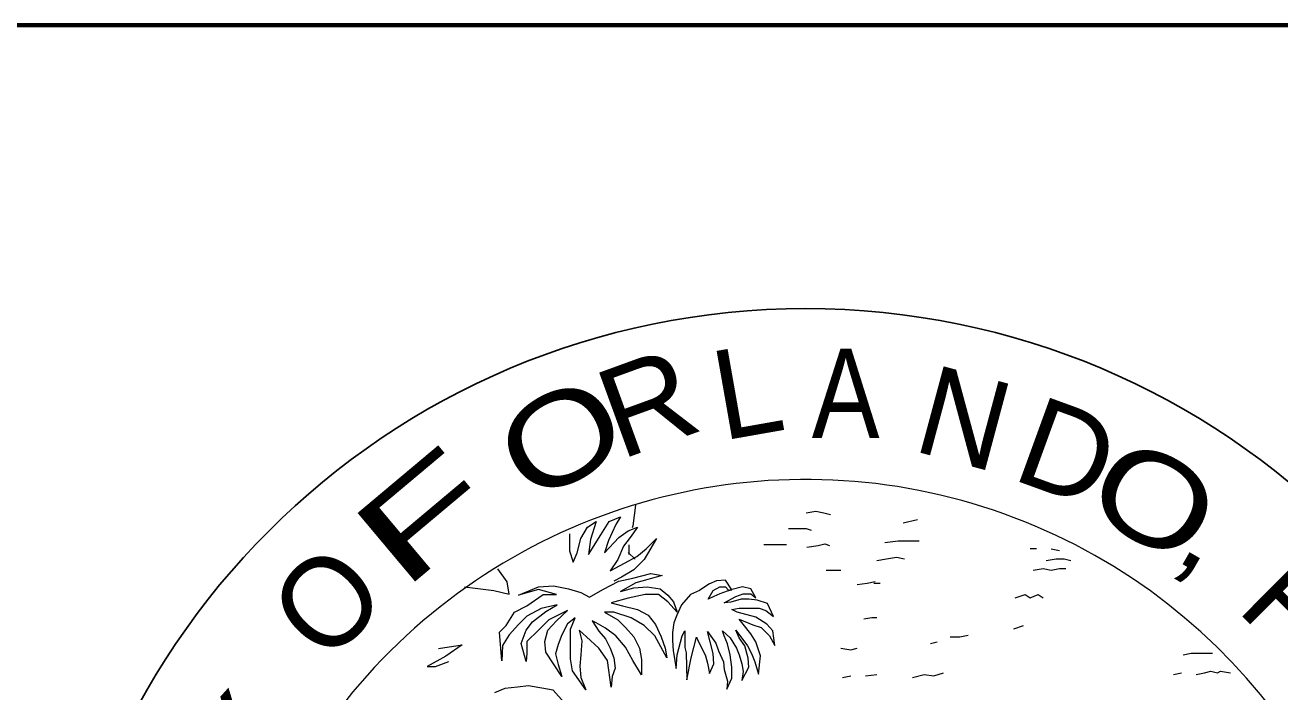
# Model space of a CAD drawing. Extents: x 44.6 to 61.6, y -38.7 to -27.7.
# Drawn here: x 46.005 to 46.645, y -37.305 to -36.965 of the extents above; entities that cross this region are included whole.
import ezdxf
from ezdxf.enums import TextEntityAlignment as Align

# ---------------------------------------------------------------- set-up
doc = ezdxf.new("R2010")
doc.units = 0
doc.header["$LTSCALE"] = 0.025
doc.layers.add('60', color=7, linetype='Continuous', lineweight=13)

msp = doc.modelspace()

# ---------------------------------------------------------------- linework, layer by layer
at = {"layer": '60', "lineweight": 70}
msp.add_line((48.84124, -36.96462), (44.82119, -36.96462), dxfattribs=at)
at = {"layer": '60'}
for p, q in [((46.45297, -37.21851), (46.46042, -37.21686)), ((46.31307, -37.22979), (46.31307, -37.23475)), ((46.31272, -37.23374), (46.31639, -37.23711)), ((46.52111, -37.23182), (46.51776, -37.23182)), ((46.52858, -37.23182), (46.53274, -37.23268)), ((46.43801, -37.24929), (46.44129, -37.24929)), ((46.50944, -37.27259), (46.51441, -37.2709)), ((46.46703, -37.28004), (46.4704, -37.27919)), ((46.42218, -37.2975), (46.42631, -37.29666)), ((46.4338, -37.29666), (46.43961, -37.29582)), ((46.59091, -37.29582), (46.59507, -37.295))]:
    msp.add_line(p, q, dxfattribs=at)
for points in [[(46.31657, -37.20958), (46.31586, -37.21485), (46.31516, -37.22007), (46.31473, -37.22114)], [(46.2829, -37.22417), (46.2829, -37.23284), (46.28478, -37.23862), (46.28672, -37.23383), (46.28864, -37.22657), (46.29208, -37.22076), (46.29639, -37.21787), (46.2935, -37.22705), (46.29251, -37.23475), (46.29877, -37.22466), (46.30315, -37.21787), (46.30892, -37.21545), (46.3065, -37.21934), (46.30266, -37.22757), (46.30074, -37.23383), (46.30797, -37.22605), (46.31274, -37.22268), (46.31761, -37.22076), (46.31371, -37.22605), (46.31038, -37.23043), (46.30745, -37.23721), (46.30362, -37.24293), (46.31083, -37.2391), (46.31711, -37.23572), (46.32194, -37.23184), (46.32728, -37.22657), (46.32097, -37.23721), (46.31565, -37.24248), (46.30941, -37.24633), (46.30551, -37.24827)], [(46.4035, -37.21341), (46.40847, -37.21258), (46.41265, -37.21341), (46.41596, -37.21424)], [(46.39448, -37.22149), (46.40107, -37.22149), (46.40359, -37.22149), (46.4061, -37.22232)], [(46.382, -37.2296), (46.38776, -37.2296), (46.38944, -37.2296), (46.39357, -37.2296)], [(46.40389, -37.23097), (46.4097, -37.23017), (46.41305, -37.22931), (46.41551, -37.23017)], [(46.44378, -37.22856), (46.45042, -37.22767), (46.45541, -37.22767), (46.46122, -37.22767)], [(46.43961, -37.23766), (46.4446, -37.23681), (46.44964, -37.23601), (46.45378, -37.23681)], [(46.22933, -37.2511), (46.24429, -37.25304), (46.252, -37.25496), (46.25105, -37.2487), (46.24621, -37.24196)], [(46.41383, -37.24265), (46.41797, -37.24265), (46.42132, -37.24265)], [(46.51942, -37.24265), (46.52443, -37.24182), (46.52858, -37.24265), (46.53274, -37.24182), (46.53603, -37.24182)], [(46.52607, -37.23766), (46.53106, -37.23681), (46.53518, -37.23681), (46.53855, -37.23766)], [(46.24859, -37.28105), (46.24833, -37.28897), (46.2472, -37.27432), (46.25056, -37.27096), (46.25486, -37.26418), (46.26112, -37.2608), (46.26935, -37.25508), (46.27614, -37.25508), (46.26694, -37.25259), (46.25682, -37.25546), (46.26694, -37.25118), (46.27465, -37.25071), (46.28238, -37.25212), (46.28864, -37.25408), (46.29299, -37.25645), (46.29977, -37.25259), (46.30797, -37.24827), (46.31516, -37.2468), (46.32432, -37.24445), (46.33017, -37.24536), (46.31665, -37.2492), (46.30892, -37.25356), (46.31565, -37.25168), (46.32239, -37.25118), (46.32917, -37.25212), (46.333, -37.25546), (46.33596, -37.25886), (46.33784, -37.26418), (46.333, -37.25886), (46.3282, -37.25508), (46.32144, -37.25508), (46.31274, -37.25697), (46.30407, -37.25935), (46.30989, -37.2608), (46.31761, -37.26274), (46.32291, -37.26559), (46.32676, -37.27044), (46.32967, -37.27671), (46.33158, -37.28252), (46.33257, -37.28732), (46.32629, -37.27623), (46.32097, -37.27096), (46.31423, -37.26706), (46.30551, -37.26418), (46.30074, -37.26418), (46.30745, -37.26805), (46.31132, -37.27191), (46.31565, -37.27671), (46.3186, -37.28252), (46.31953, -37.28831), (46.31953, -37.29602), (46.31516, -37.28878), (46.31132, -37.28202), (46.3065, -37.27623), (46.30119, -37.27233), (46.29639, -37.26947), (46.29445, -37.26855), (46.29783, -37.27382), (46.30119, -37.2777), (46.30362, -37.28252), (46.30551, -37.28732), (46.30605, -37.29261), (46.30456, -37.29699), (46.30407, -37.3023), (46.30216, -37.28878), (46.29783, -37.28252), (46.29154, -37.27671), (46.28769, -37.27332), (46.28916, -37.27867), (46.28864, -37.2859), (46.28819, -37.29167), (46.28864, -37.29748), (46.29109, -37.30375), (46.28429, -37.2941), (46.28331, -37.28783), (46.28331, -37.27961), (46.28331, -37.27285), (46.28577, -37.26706), (46.2819, -37.26997), (46.27899, -37.27574), (46.27707, -37.28056), (46.27564, -37.28543), (46.27707, -37.29072), (46.27899, -37.29699), (46.27081, -37.28446), (46.27032, -37.27911), (46.27174, -37.27332), (46.27614, -37.26855), (46.2819, -37.26323), (46.27226, -37.26805), (46.26694, -37.27332), (46.26112, -37.27911), (46.26112, -37.28493), (46.26068, -37.28928), (46.25826, -37.28014), (46.26068, -37.27332), (46.26403, -37.26898), (46.27081, -37.26369), (46.27662, -37.26035), (46.26841, -37.26224)], [(46.42967, -37.25007), (46.43466, -37.24929), (46.43879, -37.24846)], [(46.51026, -37.2568), (46.51525, -37.2551), (46.51776, -37.2568), (46.5219, -37.2551), (46.52443, -37.2568)], [(46.26841, -37.26224), (46.26112, -37.26607), (46.25682, -37.27044), (46.252, -37.27574), (46.24859, -37.28105)], [(46.43296, -37.26758), (46.43711, -37.26676), (46.43961, -37.26676)], [(46.216, -37.28259), (46.22806, -37.28068), (46.21983, -37.28647), (46.21021, -37.29176), (46.21456, -37.29176), (46.22132, -37.28935)], [(46.47705, -37.27671), (46.48202, -37.27671), (46.48616, -37.27587)], [(46.42132, -37.28254), (46.42631, -37.28337), (46.42967, -37.28254)], [(46.5959, -37.28587), (46.60001, -37.28505), (46.60422, -37.28505), (46.6067, -37.28505), (46.61083, -37.28505)], [(46.60258, -37.29582), (46.6067, -37.295), (46.61003, -37.29415), (46.61334, -37.295), (46.61499, -37.29415), (46.62, -37.295)], [(46.45789, -37.2975), (46.4637, -37.29582), (46.46872, -37.29666), (46.47368, -37.295)], [(46.28005, -37.31015), (46.27457, -37.30391), (46.26195, -37.30176), (46.2563, -37.30237), (46.2499, -37.30301), (46.24465, -37.3053)]]:
    msp.add_lwpolyline(points, dxfattribs=at)
msp.add_lwpolyline([(46.33572, -37.28386), (46.33723, -37.29288), (46.33784, -37.28593), (46.3403, -37.27611), (46.34168, -37.27368), (46.34168, -37.27611), (46.34168, -37.27891), (46.34168, -37.28205), (46.34243, -37.28489), (46.34276, -37.29854), (46.34486, -37.28732), (46.34763, -37.27684), (46.34872, -37.27928), (46.35044, -37.28276), (46.35222, -37.2863), (46.35325, -37.29014), (46.35434, -37.29541), (46.35643, -37.29049), (46.35606, -37.28522), (46.35468, -37.27928), (46.35325, -37.27399), (46.35746, -37.27997), (46.35887, -37.28386), (46.36133, -37.2894), (46.36167, -37.29327), (46.36342, -37.29925), (46.36308, -37.30346), (46.36557, -37.29783), (46.36557, -37.29223), (46.36483, -37.28593), (46.36342, -37.28032), (46.36167, -37.27611), (46.36096, -37.27368), (46.36483, -37.27714), (46.368, -37.28241), (46.36937, -37.28593), (46.37079, -37.29049), (46.37146, -37.29439), (46.37079, -37.2989), (46.37433, -37.29223), (46.37394, -37.28765), (46.37221, -37.28133), (46.36937, -37.27714), (46.36762, -37.2733), (46.37358, -37.28133), (46.37569, -37.28522), (46.37741, -37.2894), (46.37923, -37.29573), (46.38025, -37.2863), (46.37781, -37.27928), (46.37535, -37.27507), (46.37146, -37.27016), (46.36937, -37.26773), (46.37637, -37.27049), (46.3806, -37.27196), (46.38478, -37.27611), (46.38759, -37.28103), (46.38653, -37.27368), (46.38342, -37.27016), (46.37781, -37.26664), (46.36831, -37.26418), (46.36557, -37.26281), (46.36937, -37.2621), (46.37465, -37.2621), (46.37954, -37.2621), (46.38303, -37.26317), (46.38689, -37.26633), (46.38377, -37.25967), (46.37852, -37.25792), (46.37433, -37.25754), (46.37044, -37.25754), (46.36515, -37.25893), (46.36167, -37.25926), (46.36762, -37.25617), (46.37146, -37.25475), (46.37535, -37.25475), (46.37781, -37.25683), (46.37535, -37.25227), (46.37112, -37.25125), (46.36515, -37.25263), (46.35954, -37.25475), (46.35643, -37.25617), (46.35358, -37.25754), (46.35606, -37.25304), (46.35954, -37.25125), (46.36238, -37.25125), (46.36377, -37.25263), (46.36413, -37.25304), (46.36557, -37.25263), (46.36238, -37.24775), (46.35779, -37.24808), (46.35399, -37.24985), (46.34909, -37.25304), (46.34449, -37.2551), (46.33995, -37.26035), (46.33751, -37.26559), (46.33605, -37.26947), (46.33539, -37.27439), (46.33539, -37.27857)], close=True, dxfattribs=at)
at = {"layer": '60', "lineweight": 25}
msp.add_arc((46.40331, -37.49665), 0.38741, 0, 180, dxfattribs=at)
at = {"layer": '60'}
msp.add_arc((46.40331, -37.49665), 0.30024, 359.20516, 270.606, dxfattribs=at)

# ---------------------------------------------------------------- texts
for s, rotation, width, p in [('R', 20, 1.05, (46.3304, -37.17867)), ('O', 30, 1.3, (46.28987, -37.19492)), ('D', 340, 1.05, (46.52919, -37.20377)), ('F', 40, 1.8, (46.22286, -37.2327)), ('O', 330, 1.3, (46.56984, -37.22647)), (',', 330, 1.05, (46.59816, -37.24112))]:
    msp.add_text(s, height=0.04564, rotation=rotation, dxfattribs=dict(at, width=width)).set_placement(p, align=Align.CENTER)
for s, rotation, p in [('L', 10, (46.3776, -37.1737)), ('N', 345, (46.47834, -37.18718)), ('O', 45, (46.17527, -37.27482)), ('F', 315.189, (46.63573, -37.27589)), ('Y', 48, (46.13006, -37.34726))]:
    msp.add_text(s, height=0.04564, rotation=rotation, dxfattribs=at).set_placement(p, align=Align.CENTER)
at = {"layer": '60', "width": 0.85}
msp.add_text('A', height=0.04564, dxfattribs=at).set_placement((46.42371, -37.17528), align=Align.CENTER)

doc.saveas('drawing.dxf')
